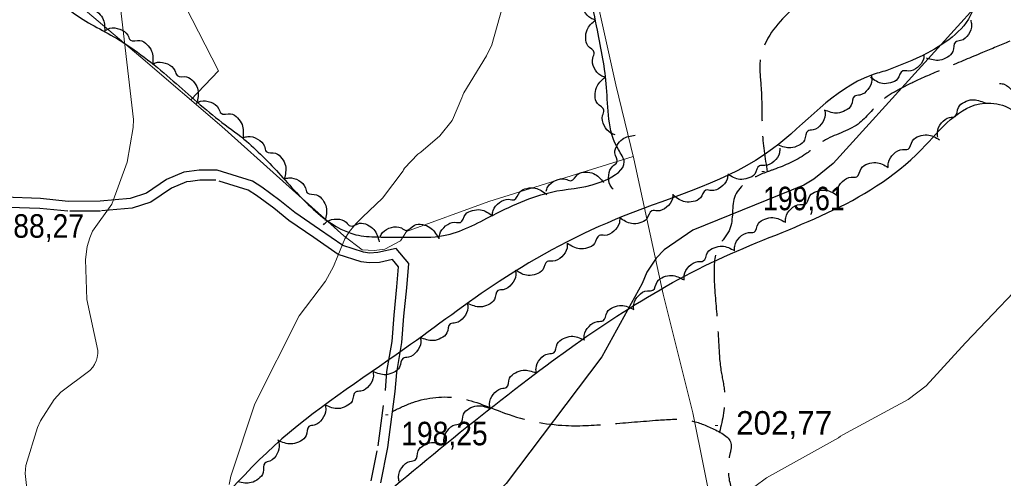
# Model space of a CAD drawing. Extents: x 480269 to 484877, y 4383588 to 4386804.
# Drawn here: x 482605.4 to 482971.7, y 4385773.1 to 4385943.8 of the extents above; entities that cross this region are included whole.
import ezdxf

# ---------------------------------------------------------------- set-up
doc = ezdxf.new("R2010")
doc.units = 0
doc.header["$LTSCALE"] = 3.8
doc.linetypes.add('LONG_DASHED', pattern=[7.5, 6, -1.5])
doc.linetypes.add('MEDIUM_DASHED', pattern=[4.5, 3, -1.5])
for name, color, linetype, lineweight in [('27', 7, 'Continuous', 25), ('38', 7, 'Continuous', 25), ('51', 7, 'Continuous', 13), ('7', 7, 'Continuous', 13), ('8', 7, 'Continuous', 25), ('9', 7, 'Continuous', 13)]:
    doc.layers.add(name, color=color, linetype=linetype, lineweight=lineweight)

msp = doc.modelspace()

# ---------------------------------------------------------------- linework, layer by layer
at = {"layer": '27'}
for points in [[(482733.85, 4386450.9), (482735.83, 4386413.89), (482747.58, 4386352.79), (482763.24, 4386337.9), (482788.29, 4386326.94), (482816.48, 4386325.37), (482843.88, 4386330.85), (482870.5, 4386330.07), (482891.64, 4386317.54), (482908.08, 4386276.81), (482921.39, 4386238.42), (482913.56, 4386213.36), (482892.42, 4386177.33), (482870.5, 4386147.56), (482848.58, 4386122.49), (482840.75, 4386102.91), (482844.66, 4386087.24), (482868.15, 4386064.53), (482915.13, 4386023.8), (482943.31, 4385991.68), (482958.19, 4385968.18), (482960.54, 4385947.82), (482943.31, 4385931.37), (482928.34, 4385924.89)], [(482619.68, 4385976.6), (482626.85, 4385982.63), (482638.16, 4385991.26), (482653.8, 4386006.36), (482668.08, 4386018.44), (482693.75, 4386036.23), (482710.56, 4386045.7), (482734.17, 4386062.64), (482754.81, 4386078.44), (482763.55, 4386087.92), (482774.01, 4386097.62), (482780.61, 4386100.85), (482787.53, 4386095.36), (482793.74, 4386072.7), (482795.43, 4386062.78), (482800.36, 4386045.6), (482804.67, 4386026.78), (482809.7, 4386005.29), (482812.58, 4385982.11), (482815.32, 4385966.5), (482820.53, 4385939.89), (482823.98, 4385918.6), (482828.37, 4385895.47), (482830.54, 4385890.92), (482823.31, 4385884.01), (482805.39, 4385880.07), (482781.7, 4385871.11), (482763.28, 4385863.45), (482750.32, 4385862.89), (482738.55, 4385862.97), (482730.64, 4385863.8), (482716.59, 4385871.65), (482702.62, 4385885.89), (482688.9, 4385899.36), (482679.56, 4385906.51), (482661.42, 4385921.97), (482641.48, 4385936.88), (482625.3, 4385946.43), (482619.23, 4385951.81), (482612.56, 4385962.9), (482615.25, 4385967.22), (482619.06, 4385974.43), (482619.68, 4385976.6)], [(482928.34, 4385924.89), (482922.57, 4385923.15), (482885.78, 4385895.73), (482830.19, 4385870.67), (482783.99, 4385846.38), (482748.76, 4385821.32), (482700.22, 4385785.28), (482658.72, 4385739.07), (482615.66, 4385695.2), (482579.64, 4385663.09), (482560.07, 4385645.07), (482539.71, 4385649.77), (482459.85, 4385672.49), (482360.42, 4385703.82), (482306.4, 4385727.32), (482257.85, 4385789.2), (482191.3, 4385880.85), (482166.25, 4385912.96), (482169.38, 4385923.15), (482197.57, 4385932.55), (482218.71, 4385942.73), (482235.93, 4385961.53), (482260.99, 4385957.61), (482288.39, 4385973.28), (482296.22, 4385991.3), (482306.4, 4385999.91), (482324.4, 4386001.48), (482354.16, 4385995.21), (482372.16, 4385973.28), (482387.82, 4385970.15), (482414.44, 4385988.16), (482434.02, 4385990.51), (482466.12, 4385956.05), (482473.95, 4385954.08)], [(482819.81, 4385943.75), (482818.13, 4385944.34), (482815.6, 4385947.16), (482814.99, 4385950.8), (482815.49, 4385952.8), (482812.98, 4385955.32), (482812.11, 4385958.17), (482812.52, 4385961.17), (482815.62, 4385965.04)], [(482618.34, 4385950.47), (482619.89, 4385951.34), (482623.68, 4385951.38), (482626.82, 4385949.44), (482627.99, 4385947.75), (482631.54, 4385947.96), (482634.25, 4385946.73), (482636.24, 4385944.45), (482637.1, 4385939.56)], [(482637.3, 4385939.89), (482638.93, 4385940.61), (482642.71, 4385940.27), (482645.64, 4385938.03), (482646.64, 4385936.23), (482650.19, 4385936.1), (482652.77, 4385934.61), (482654.52, 4385932.14), (482654.9, 4385927.19)], [(482823.44, 4385922.37), (482821.78, 4385923.01), (482819.34, 4385925.9), (482818.84, 4385929.56), (482819.39, 4385931.54), (482816.96, 4385934.14), (482816.18, 4385937.02), (482816.68, 4385940), (482819.89, 4385943.78)], [(482959.55, 4385943.7), (482959.87, 4385941.95), (482958.68, 4385938.35), (482955.82, 4385936.02), (482953.85, 4385935.46), (482952.9, 4385932.03), (482950.86, 4385929.85), (482948.05, 4385928.72), (482943.15, 4385929.49)], [(482942.19, 4385930.89), (482941.97, 4385929.12), (482939.75, 4385926.05), (482936.32, 4385924.68), (482934.27, 4385924.74), (482932.33, 4385921.76), (482929.73, 4385920.3), (482926.71, 4385920.07), (482922.27, 4385922.27)], [(482655.05, 4385927.39), (482656.73, 4385927.97), (482660.47, 4385927.33), (482663.21, 4385924.86), (482664.06, 4385922.99), (482667.59, 4385922.57), (482670.05, 4385920.88), (482671.59, 4385918.28), (482671.57, 4385913.32)], [(482922.57, 4385923.15), (482922.76, 4385921.39), (482921.31, 4385917.88), (482918.28, 4385915.76), (482916.27, 4385915.35), (482915.08, 4385912), (482912.87, 4385909.99), (482910, 4385909.06), (482905.16, 4385910.19)], [(482827.18, 4385901.01), (482825.52, 4385901.62), (482823.03, 4385904.48), (482822.47, 4385908.13), (482823, 4385910.11), (482820.53, 4385912.67), (482819.7, 4385915.54), (482820.15, 4385918.53), (482823.31, 4385922.36)], [(482970.34, 4385920.13), (482972.08, 4385919.77), (482974.96, 4385917.3), (482976.04, 4385913.77), (482975.82, 4385911.73), (482978.63, 4385909.56), (482979.87, 4385906.84), (482979.86, 4385903.82), (482977.29, 4385899.57)], [(482599.89, 4385643.3), (482628.86, 4385671.49), (482714.99, 4385745.13), (482794.85, 4385810.14), (482867.67, 4385855.58), (482941.27, 4385895.53), (482964.76, 4385912.76), (482973.37, 4385911.19), (482981.98, 4385879.86), (482998.42, 4385827.38), (483006.25, 4385814.84), (483025.83, 4385810.93), (483050.88, 4385818.76), (483058.71, 4385808.58), (483056.36, 4385779.59), (483052.45, 4385741.21), (483034.44, 4385691.86), (483035.22, 4385677.76), (483043.84, 4385669.93), (483091.6, 4385655.04), (483126.05, 4385633.11), (483147.97, 4385609.61), (483156.58, 4385589.25), (483155.8, 4385568.88), (483155.02, 4385552.43), (483155.02, 4385532.85), (483155.02, 4385519.53), (483152.67, 4385510.13)], [(482671.13, 4385912.78), (482672.77, 4385913.47), (482676.54, 4385913.08), (482679.44, 4385910.79), (482680.41, 4385908.98), (482683.96, 4385908.8), (482686.52, 4385907.27), (482688.23, 4385904.77), (482688.54, 4385899.82)], [(482947.32, 4385900.12), (482947.15, 4385901.89), (482948.65, 4385905.37), (482951.7, 4385907.45), (482953.72, 4385907.84), (482954.96, 4385911.17), (482957.19, 4385913.15), (482960.08, 4385914.04), (482964.9, 4385912.85)], [(482905.17, 4385910.18), (482905.36, 4385908.42), (482903.91, 4385904.91), (482900.88, 4385902.8), (482898.87, 4385902.38), (482897.68, 4385899.03), (482895.48, 4385897.02), (482892.6, 4385896.1), (482887.77, 4385897.22)], [(482826.4, 4385880.8), (482825.32, 4385882.21), (482824.76, 4385885.96), (482826.26, 4385889.33), (482827.77, 4385890.73), (482827.07, 4385894.21), (482827.91, 4385897.07), (482829.9, 4385899.35), (482834.62, 4385900.88)], [(482928.87, 4385888.85), (482928.93, 4385890.62), (482930.88, 4385893.87), (482934.18, 4385895.53), (482936.23, 4385895.64), (482937.91, 4385898.78), (482940.38, 4385900.46), (482943.36, 4385900.95), (482947.98, 4385899.13)], [(482688.62, 4385899.9), (482690.34, 4385900.34), (482694.02, 4385899.41), (482696.55, 4385896.72), (482697.24, 4385894.79), (482700.73, 4385894.09), (482703.04, 4385892.2), (482704.37, 4385889.49), (482703.95, 4385884.54)], [(482888.46, 4385896.05), (482888.34, 4385894.27), (482886.3, 4385891.08), (482882.95, 4385889.53), (482880.9, 4385889.47), (482879.13, 4385886.38), (482876.61, 4385884.79), (482873.61, 4385884.38), (482869.06, 4385886.34)], [(482909.77, 4385878.55), (482909.83, 4385880.32), (482911.78, 4385883.58), (482915.08, 4385885.23), (482917.13, 4385885.35), (482918.8, 4385888.49), (482921.28, 4385890.16), (482924.26, 4385890.65), (482928.87, 4385888.84)], [(482801.42, 4385879.95), (482802.08, 4385881.6), (482805, 4385884.02), (482808.66, 4385884.47), (482810.64, 4385883.9), (482813.26, 4385886.3), (482816.15, 4385887.05), (482819.12, 4385886.52), (482822.87, 4385883.27)], [(482869.13, 4385886.18), (482868.83, 4385884.43), (482866.48, 4385881.45), (482863, 4385880.23), (482860.95, 4385880.38), (482858.89, 4385877.48), (482856.23, 4385876.14), (482853.21, 4385876.03), (482848.86, 4385878.42)], [(482703.93, 4385884.53), (482705.65, 4385884.96), (482709.32, 4385884), (482711.82, 4385881.29), (482712.51, 4385879.35), (482715.99, 4385878.62), (482718.28, 4385876.72), (482719.59, 4385873.99), (482719.13, 4385869.05)], [(482781.44, 4385871.01), (482781.73, 4385872.76), (482784.08, 4385875.74), (482787.56, 4385876.96), (482789.61, 4385876.81), (482791.67, 4385879.71), (482794.33, 4385881.05), (482797.36, 4385881.16), (482801.7, 4385878.77)], [(482848.65, 4385878.92), (482848.46, 4385877.15), (482846.27, 4385874.05), (482842.86, 4385872.65), (482840.8, 4385872.68), (482838.9, 4385869.68), (482836.32, 4385868.19), (482833.3, 4385867.92), (482828.84, 4385870.08)], [(482890.61, 4385868.36), (482890.68, 4385870.13), (482892.65, 4385873.38), (482895.96, 4385875.02), (482898.01, 4385875.12), (482899.69, 4385878.25), (482902.17, 4385879.92), (482905.16, 4385880.4), (482909.76, 4385878.56)], [(482761.61, 4385862.21), (482761.82, 4385863.97), (482764.04, 4385867.05), (482767.47, 4385868.42), (482769.52, 4385868.37), (482771.45, 4385871.36), (482774.05, 4385872.82), (482777.07, 4385873.06), (482781.51, 4385870.86)], [(482718.54, 4385867.5), (482719.85, 4385868.7), (482723.53, 4385869.6), (482727.03, 4385868.42), (482728.55, 4385867.04), (482731.96, 4385868.06), (482734.89, 4385867.48), (482737.34, 4385865.7), (482739.29, 4385861.14)], [(482739.63, 4385863.1), (482740.56, 4385864.61), (482743.85, 4385866.49), (482747.54, 4385866.31), (482749.38, 4385865.4), (482752.38, 4385867.31), (482755.36, 4385867.55), (482758.2, 4385866.52), (482761.32, 4385862.66)], [(482828.86, 4385870.02), (482828.72, 4385868.25), (482826.64, 4385865.08), (482823.28, 4385863.56), (482821.22, 4385863.53), (482819.42, 4385860.47), (482816.88, 4385858.89), (482813.88, 4385858.52), (482809.35, 4385860.53)], [(482871.64, 4385857.82), (482871.68, 4385859.59), (482873.56, 4385862.88), (482876.83, 4385864.6), (482878.88, 4385864.75), (482880.49, 4385867.92), (482882.93, 4385869.64), (482885.91, 4385870.19), (482890.55, 4385868.46)], [(482809.31, 4385860.6), (482809.23, 4385858.83), (482807.25, 4385855.59), (482803.93, 4385853.97), (482801.88, 4385853.87), (482800.18, 4385850.75), (482797.69, 4385849.1), (482794.71, 4385848.63), (482790.11, 4385850.5)], [(482852.84, 4385846.98), (482852.85, 4385848.75), (482854.7, 4385852.07), (482857.95, 4385853.82), (482859.99, 4385854.01), (482861.56, 4385857.19), (482863.98, 4385858.94), (482866.95, 4385859.53), (482871.62, 4385857.86)], [(482790.03, 4385850.58), (482790.16, 4385848.81), (482788.59, 4385845.36), (482785.5, 4385843.34), (482783.48, 4385842.99), (482782.17, 4385839.68), (482779.91, 4385837.74), (482777, 4385836.91), (482772.21, 4385838.2)], [(482834.07, 4385836.09), (482834.08, 4385837.87), (482835.93, 4385841.18), (482839.18, 4385842.94), (482841.22, 4385843.12), (482842.79, 4385846.31), (482845.21, 4385848.06), (482848.18, 4385848.64), (482852.85, 4385846.97)], [(482772.12, 4385838.32), (482772.29, 4385836.55), (482770.8, 4385833.06), (482767.75, 4385830.98), (482765.74, 4385830.59), (482764.5, 4385827.26), (482762.28, 4385825.27), (482759.39, 4385824.38), (482754.57, 4385825.56)], [(482815.7, 4385824.54), (482815.66, 4385826.31), (482817.42, 4385829.68), (482820.61, 4385831.52), (482822.65, 4385831.76), (482824.14, 4385834.99), (482826.51, 4385836.8), (482829.46, 4385837.47), (482834.17, 4385835.93)], [(482754.61, 4385825.5), (482754.77, 4385823.73), (482753.24, 4385820.26), (482750.17, 4385818.2), (482748.16, 4385817.83), (482746.89, 4385814.51), (482744.65, 4385812.54), (482741.75, 4385811.67), (482736.94, 4385812.9)], [(482797.83, 4385812.24), (482797.68, 4385814.01), (482799.23, 4385817.47), (482802.31, 4385819.51), (482804.33, 4385819.87), (482805.62, 4385823.18), (482807.87, 4385825.14), (482810.78, 4385825.98), (482815.58, 4385824.73)], [(482736.95, 4385812.89), (482737.11, 4385811.12), (482735.58, 4385807.65), (482732.51, 4385805.6), (482730.49, 4385805.23), (482729.23, 4385801.9), (482726.98, 4385799.93), (482724.09, 4385799.07), (482719.28, 4385800.3)], [(482780.59, 4385799.07), (482780.36, 4385800.83), (482781.74, 4385804.36), (482784.73, 4385806.54), (482786.73, 4385806.99), (482787.86, 4385810.36), (482790.02, 4385812.42), (482792.88, 4385813.4), (482797.73, 4385812.37)], [(482719.14, 4385800.47), (482719.39, 4385798.72), (482718.07, 4385795.16), (482715.12, 4385792.94), (482713.13, 4385792.45), (482712.05, 4385789.06), (482709.92, 4385786.97), (482707.08, 4385785.94), (482702.21, 4385786.89)], [(482763.62, 4385785.54), (482763.36, 4385787.3), (482764.67, 4385790.86), (482767.61, 4385793.09), (482769.6, 4385793.59), (482770.66, 4385796.98), (482772.78, 4385799.08), (482775.62, 4385800.12), (482780.49, 4385799.19)], [(482701.55, 4385787.58), (482702.05, 4385785.88), (482701.23, 4385782.17), (482698.62, 4385779.56), (482696.71, 4385778.8), (482696.12, 4385775.3), (482694.3, 4385772.93), (482691.63, 4385771.52), (482686.67, 4385771.78)], [(482746.75, 4385771.89), (482746.49, 4385773.64), (482747.8, 4385777.2), (482750.74, 4385779.44), (482752.73, 4385779.93), (482753.8, 4385783.33), (482755.92, 4385785.43), (482758.76, 4385786.47), (482763.63, 4385785.53)]]:
    msp.add_spline(points, degree=3, dxfattribs=at)
at = {"layer": '38'}
msp.add_lwpolyline([(482739.95, 4385771.48), (482742.5, 4385784.58), (482743.05, 4385788.48), (482745.25, 4385805.41), (482745.82, 4385812.47), (482747.77, 4385823.62), (482748.51, 4385833.51), (482749.56, 4385844.08), (482750.28, 4385853.08), (482745.56, 4385858.65), (482738.83, 4385857.17), (482735.65, 4385856.97), (482733.39, 4385857.25), (482725.69, 4385859.76), (482717.05, 4385865.76), (482707.84, 4385872.08), (482702.25, 4385876.56), (482695.63, 4385881.45), (482692.14, 4385883.69), (482679.01, 4385887.82), (482672.19, 4385887.77), (482668.53, 4385887.27), (482666.52, 4385887.03), (482660.13, 4385884.32), (482652.6, 4385879.24), (482646.54, 4385877.29), (482635.33, 4385876.29), (482623.48, 4385876.19), (482613.17, 4385877.27), (482599.58, 4385877.71)], dxfattribs=at)
at = {"layer": '38', "linetype": 'MEDIUM_DASHED'}
msp.add_lwpolyline([(482736.34, 4385772.19), (482738.87, 4385785.2), (482739.4, 4385788.98), (482741.58, 4385805.8), (482742.15, 4385812.92), (482744.1, 4385824.08), (482744.84, 4385833.84), (482745.89, 4385844.41), (482746.49, 4385851.86), (482744.19, 4385854.56), (482739.35, 4385853.5), (482735.53, 4385853.27), (482732.57, 4385853.64), (482724.03, 4385856.43), (482714.96, 4385862.72), (482705.65, 4385869.12), (482700, 4385873.63), (482693.55, 4385878.41), (482690.55, 4385880.33), (482678.45, 4385884.13), (482672.46, 4385884.09), (482669, 4385883.61), (482667.48, 4385883.44), (482661.9, 4385881.06), (482654.23, 4385875.9), (482647.27, 4385873.66), (482635.52, 4385872.6), (482623.31, 4385872.5), (482612.92, 4385873.58), (482599.59, 4385874.02)], dxfattribs=at)
at = {"layer": '38', "linetype": 'LONG_DASHED'}
for points in [[(482919.81, 4386032.46), (482916.47, 4386023.76), (482913.46, 4385999.27), (482908.31, 4385970.7), (482901.88, 4385956.25), (482891.28, 4385945.96), (482881.21, 4385928.9), (482881.45, 4385919.25), (482881.85, 4385905.72), (482881.92, 4385902.8), (482883.81, 4385887.17)], [(482974.09, 4385935.79), (482963.93, 4385931.55), (482951.04, 4385926.16), (482939.98, 4385921.39), (482932.4, 4385917.58), (482926.17, 4385913.49), (482917.6, 4385904.99), (482904.71, 4385898.65), (482898.15, 4385893.84), (482886.24, 4385888.07), (482881.79, 4385886.42), (482871.88, 4385878.41), (482869.75, 4385865.65), (482865.84, 4385859.61), (482864, 4385848.32), (482865.13, 4385832.17), (482865.64, 4385824.31), (482866.57, 4385813.28), (482867.95, 4385804.59), (482866.03, 4385790.28)], [(482744.29, 4385798.04), (482751.76, 4385801.34), (482769.09, 4385802.98), (482786.38, 4385797.29), (482808.74, 4385792.77), (482825.58, 4385793.37), (482843.25, 4385794.8), (482854.92, 4385794.68), (482863.36, 4385791.69), (482870.36, 4385785.68), (482869.92, 4385782.24), (482869.67, 4385772.3), (482873.58, 4385762.53), (482880.22, 4385746.55), (482883.53, 4385738.15), (482891.02, 4385720.62), (482898.5, 4385699.42), (482905.2, 4385684.64), (482910.7, 4385676.09), (482920.17, 4385664.3), (482923.56, 4385658.81), (482929.98, 4385637.62), (482930.83, 4385636.68), (482931.13, 4385618.04), (482931.31, 4385599.34), (482930.96, 4385592.88), (482932.31, 4385542.38), (482934.1, 4385533.92)]]:
    msp.add_spline(points, degree=3, dxfattribs=at)
at = {"layer": '51'}
for points in [[(482638.32, 4386451.59), (482647.62, 4386430.08), (482664.03, 4386385.87), (482680.32, 4386350.25), (482700.95, 4386299.79), (482720.35, 4386254.06), (482737.04, 4386213.63), (482755.18, 4386171.6), (482774.92, 4386123.48), (482784.21, 4386101.54), (482793.23, 4386065.76), (482804.38, 4386014.76), (482814.66, 4385977.17), (482827.44, 4385919.58), (482834.05, 4385892.04), (482844.99, 4385841.67), (482856.12, 4385797.49), (482864.39, 4385756.22), (482876.84, 4385702.59), (482886.56, 4385661.96), (482888.55, 4385653.3)], [(482669.09, 4385913.97), (482679.4, 4385924.84), (482644.9, 4385992.17)], [(482833.85, 4385892.88), (482780.13, 4385876.16), (482749.4, 4385864.99), (482747.22, 4385861.52), (482741.42, 4385858.44), (482737.36, 4385857.87), (482732.95, 4385858.22), (482726.16, 4385863.39), (482680.69, 4385904.05), (482650.53, 4385929.81), (482610.8, 4385963.47)]]:
    msp.add_lwpolyline(points, dxfattribs=at)
at = {"layer": '7'}
for p, q in [((482881.73, 4385887.27), (482882.73, 4385887.27)), ((482741.64, 4385796.7), (482742.64, 4385796.7)), ((482864.4, 4385792.81), (482865.4, 4385792.81))]:
    msp.add_line(p, q, dxfattribs=at)
at = {"layer": '8'}
msp.add_lwpolyline([(482974.08, 4385962.84), (482908.38, 4385890.3), (482901.16, 4385884.48), (482897.39, 4385882.24), (482856.09, 4385865.5), (482845.35, 4385858.2), (482842.41, 4385855.01), (482838.9, 4385849.82), (482837.2, 4385845.61), (482822.15, 4385818.3), (482786.6, 4385771.14), (482760.71, 4385746.91), (482743.87, 4385727.8), (482719.64, 4385704.84), (482717.19, 4385701.35), (482716.5, 4385699.87), (482711.72, 4385686.41), (482711.08, 4385682.92), (482710.31, 4385667.5), (482711.27, 4385657.05), (482716.96, 4385635.42), (482725.53, 4385614.77), (482731.4, 4385605.41), (482741.47, 4385596.43)], dxfattribs=at)
at = {"layer": '9'}
for points in [[(482797.35, 4385992.02), (482781.24, 4385934.46), (482779.3, 4385930.39), (482770.84, 4385916.64), (482770.41, 4385915.71), (482770.06, 4385914.68), (482766.58, 4385906.57), (482766.42, 4385906.29), (482761.85, 4385900.57), (482754.85, 4385894.47), (482754.36, 4385894.23), (482753.66, 4385893.73), (482748.74, 4385888.62), (482748.28, 4385887.96), (482748.23, 4385887.62), (482740.57, 4385877.35), (482733.05, 4385870.3), (482730.53, 4385867.87), (482728.07, 4385864.85), (482726.48, 4385862.26), (482723.83, 4385855.93), (482722.26, 4385851.98), (482719.24, 4385846.55), (482709.44, 4385833.54), (482693.03, 4385800.86), (482683.99, 4385773.91), (482683.47, 4385770.86)], [(482642.25, 4385954.78), (482647.78, 4385906.69), (482647.67, 4385903.7), (482645.46, 4385890.81), (482639.7, 4385875.14), (482632.57, 4385865.06), (482631.5, 4385862.62), (482630.55, 4385859.36), (482629.86, 4385854.58), (482630.42, 4385839.74), (482634.45, 4385820.64), (482634.47, 4385819.63), (482634.32, 4385818.13), (482634.05, 4385817.16), (482633.94, 4385816.87)], [(482985.73, 4385853), (482957.76, 4385823.73), (482957.67, 4385823.6), (482942.96, 4385807.55), (482936.29, 4385802.45), (482912, 4385789.36), (482911.07, 4385788.8), (482910.27, 4385788.2), (482883.46, 4385773.31), (482874.87, 4385766.85)], [(482633.94, 4385816.87), (482633.25, 4385815.49), (482632.59, 4385814.46), (482631.59, 4385813.28), (482620.76, 4385805.24), (482618.29, 4385802.47), (482613.2, 4385794.52), (482612.1, 4385792.01), (482607.72, 4385777.96), (482607.43, 4385774.96), (482611.44, 4385738.74)]]:
    msp.add_lwpolyline(points, dxfattribs=at)

# ---------------------------------------------------------------- texts
at = {"layer": '7'}
for s, width, p in [('199,61', 0.85, (482882.23, 4385872.9)), ('188,27', 0.9, (482597.16, 4385862.67)), ('198,25', 0.9, (482747.48, 4385785.42))]:
    msp.add_text(s, height=8.75, dxfattribs=dict(at, width=width)).set_placement(p)
msp.add_text('202,77', height=8.75, dxfattribs=at).set_placement((482872.2, 4385789.39))

doc.saveas('drawing.dxf')
